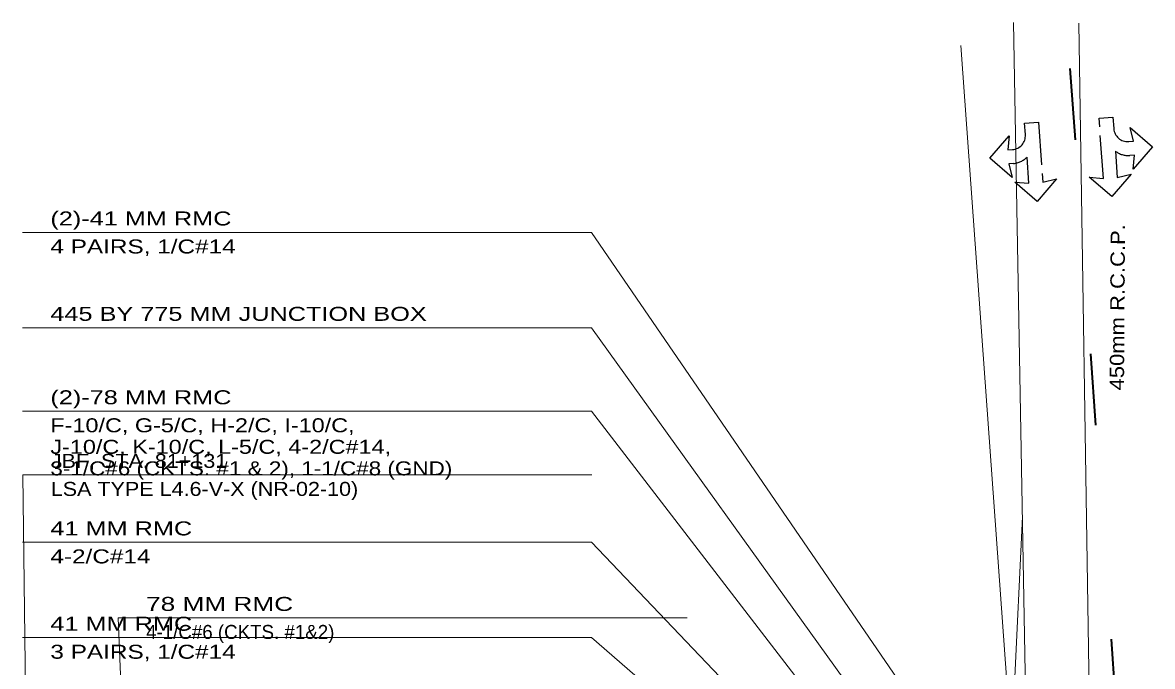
# Model space of a CAD drawing. Extents: x 168203 to 169863, y 223196 to 223870.
# Drawn here: x 168298.19 to 168345.59, y 223676.56 to 223703.56 of the extents above; entities that cross this region are included whole.
import ezdxf
from ezdxf.enums import TextEntityAlignment as Align

# ---------------------------------------------------------------- set-up
doc = ezdxf.new("R2010")
doc.units = 0
doc.header["$LTSCALE"] = 0.3
doc.linetypes.add('LONG_DASH_SHORT_DASH', pattern=[9.9, 6, -1.2, 1.5, -1.2])
for name, color, linetype, lineweight in [('1', 7, 'Continuous', 13), ('11', 7, 'Continuous', 13), ('23', 7, 'Continuous', 25), ('36', 7, 'Continuous', 35), ('9', 7, 'Continuous', 13)]:
    doc.layers.add(name, color=color, linetype=linetype, lineweight=lineweight)

msp = doc.modelspace()

# ---------------------------------------------------------------- linework, layer by layer
at = {"layer": '1'}
msp.add_line((168337.5591, 223702.6003), (168340.1802, 223666.3325), dxfattribs=at)
at = {"layer": '11'}
for p, q in [((168298.5278, 223655.5013), (168298.2028, 223684.5932)), ((168322.0763, 223684.5932), (168298.2028, 223684.5932)), ((168303.1203, 223655.5636), (168302.2028, 223678.5932)), ((168326.0763, 223678.5932), (168302.2028, 223678.5932))]:
    msp.add_line(p, q, dxfattribs=at)
at = {"layer": '23', "lineweight": 13}
for p, q in [((168340.3639, 223670.3485), (168339.7699, 223703.561)), ((168342.502, 223703.5394), (168343.1919, 223658.702)), ((168340.1403, 223682.8465), (168337.0072, 223618.1402))]:
    msp.add_line(p, q, dxfattribs=at)
at = {"layer": '36'}
for p, q in [((168342.358, 223698.6402), (168342.1417, 223701.6325)), ((168343.223, 223686.6715), (168343.0067, 223689.6637)), ((168345.3131, 223657.7471), (168343.8716, 223677.695))]:
    msp.add_line(p, q, dxfattribs=at)
at = {"layer": '36', "linetype": 'LONG_DASH_SHORT_DASH', "lineweight": 25}
for points in [[(168344.0397, 223698.1682), (168344.1192, 223697.0697), (168344.6958, 223697.2091), (168343.8836, 223696.2703), (168342.9448, 223697.0825), (168343.5355, 223697.0275), (168343.3526, 223699.5568), (168343.9363, 223699.599), (168343.9715, 223699.1125)], [(168340.8103, 223699.3908), (168340.9932, 223696.8615), (168341.5698, 223697.0009), (168340.7576, 223696.0621), (168339.8188, 223696.8743), (168340.4095, 223696.8193), (168340.3301, 223697.9178)], [(168340.2618, 223698.8621), (168340.2266, 223699.3486), (168340.8103, 223699.3908)], [(168344.5973, 223698.5711), (168344.7919, 223698.5851), (168344.6525, 223699.1618)], [(168344.6525, 223699.1618), (168345.5913, 223698.3496), (168344.7791, 223697.4107), (168344.8341, 223698.0015), (168344.6395, 223697.9874)], [(168339.7625, 223697.6526), (168339.5679, 223697.6385), (168339.7074, 223697.0619), (168338.7686, 223697.8741), (168339.5808, 223698.8129), (168339.5257, 223698.2222), (168339.7203, 223698.2363)]]:
    msp.add_lwpolyline(points, dxfattribs=at)
for centre, radius, start, end in [((168344.5552, 223699.1548), 0.5852, 184.13538, 274.13538), ((168339.6781, 223698.82), 0.5852, 274.13538, 4.13538), ((168344.5763, 223698.8629), 0.8778, 232.32592, 274.13538), ((168339.6992, 223698.5281), 0.8778, 274.13538, 315.94484)]:
    msp.add_arc(centre, radius, start, end, dxfattribs=at)
at = {"layer": '9'}
for p, q in [((168322.0601, 223694.7617), (168298.1866, 223694.7617)), ((168322.0601, 223690.7617), (168298.1866, 223690.7617)), ((168338.5814, 223667.7744), (168322.0601, 223690.7617)), ((168322.0601, 223687.2617), (168298.1866, 223687.2617)), ((168322.0601, 223681.7617), (168298.1866, 223681.7617)), ((168338.7228, 223664.3092), (168322.0601, 223681.7617)), ((168322.0601, 223677.7617), (168298.1866, 223677.7617))]:
    msp.add_line(p, q, dxfattribs=at)
for points in [[(168339.6341, 223667.9144), (168339.5071, 223669.2948), (168322.0601, 223694.7617)], [(168340.4145, 223662.1242), (168340.5555, 223663.2103), (168322.0601, 223687.2617)], [(168338.5925, 223660.394), (168339.2821, 223662.7976), (168322.0601, 223677.7617)]]:
    msp.add_lwpolyline(points, dxfattribs=at)

# ---------------------------------------------------------------- texts
at = {"layer": '11'}
for s, width, p in [('JBF, STA. 81+131             ', 1.15, (168299.3685, 223684.8824)), ('LSA TYPE L4.6-V-X (NR-02-10)          ', 1.15, (168299.3685, 223683.7077)), ('78 MM RMC                            ', 1.4, (168303.3685, 223678.8824))]:
    msp.add_text(s, height=0.5873, dxfattribs=dict(at, width=width)).set_placement(p)
msp.add_text('4-1/C#6 (CKTS. #1&2)                    ', height=0.5873, dxfattribs=at).set_placement((168303.3685, 223677.7077))
at = {"layer": '23', "width": 1.15}
msp.add_text('450mm R.C.C.P.', height=0.6, rotation=89.633, dxfattribs=at).set_placement((168344.4197, 223691.6166), align=Align.CENTER)
at = {"layer": '9'}
for s, width, p in [('(2)-41 MM RMC                        ', 1.35, (168299.3523, 223695.0509)), ('4 PAIRS, 1/C#14                      ', 1.3, (168299.3523, 223693.8762)), ('445 BY 775 MM JUNCTION BOX           ', 1.35, (168299.3523, 223691.0509)), ('(2)-78 MM RMC                          ', 1.35, (168299.3523, 223687.5509)), ('F-10/C, G-5/C, H-2/C, I-10/C,', 1.25, (168299.3523, 223686.3762)), ('J-10/C, K-10/C, L-5/C, 4-2/C#14, ', 1.25, (168299.3523, 223685.4725)), ('3-1/C#6 (CKTS. #1 & 2), 1-1/C#8 (GND) ', 1.2, (168299.3523, 223684.5689)), ('41 MM RMC                        ', 1.35, (168299.3523, 223682.0509)), ('4-2/C#14                             ', 1.3, (168299.3523, 223680.8762)), ('41 MM RMC                        ', 1.35, (168299.3523, 223678.0509)), ('3 PAIRS, 1/C#14                      ', 1.3, (168299.3523, 223676.8762))]:
    msp.add_text(s, height=0.5873, dxfattribs=dict(at, width=width)).set_placement(p)

doc.saveas('drawing.dxf')
